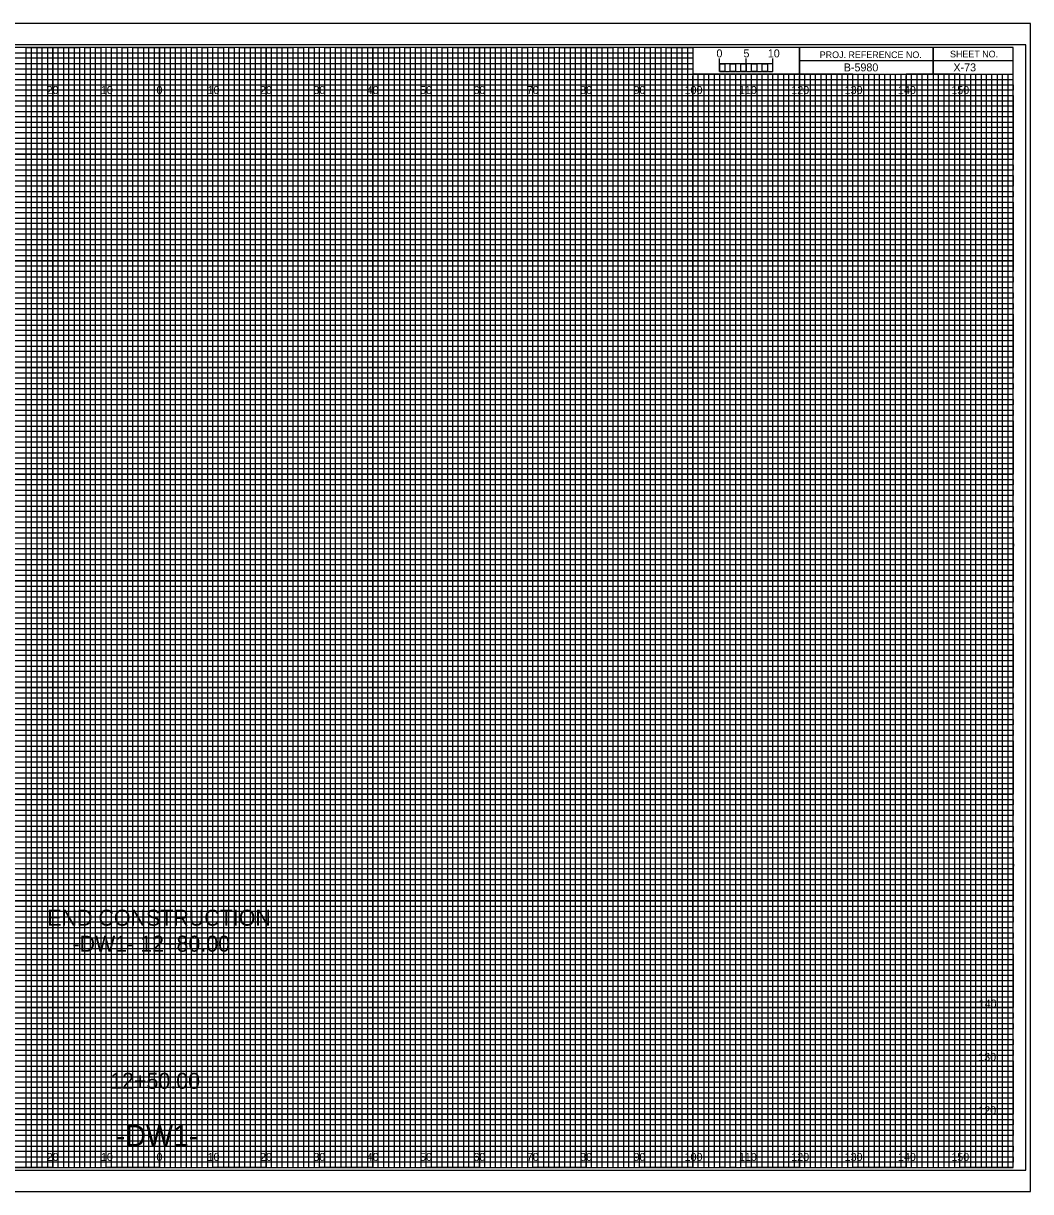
# Model space of a CAD drawing. Extents: x -13 to 323, y -5 to 434.
# Drawn here: x 134.5 to 323.3, y 215.5 to 434.5 of the extents above; entities that cross this region are included whole.
import ezdxf

# ---------------------------------------------------------------- set-up
doc = ezdxf.new("R2010")
doc.units = 0
for name, color, linetype in [('Exist Cross Section Cell', 7, 'Continuous'), ('Exist XS Center Line Elevation Label', 7, 'Continuous'), ('Exist XS Ground Line', 7, 'Continuous'), ('Prop CMT Pvmt Course 1', 7, 'Continuous'), ('Prop CMT Pvmt Course 1 Wedge', 7, 'Continuous'), ('Prop CMT Pvmt Course 2', 7, 'Continuous'), ('Prop CMT Pvmt Course 3', 7, 'Continuous'), ('Prop CMT Pvmt Surface', 7, 'Continuous'), ('Prop CMT Pvmt Surface Shoulder', 7, 'Continuous'), ('Prop CMT Shld Paved Course 1', 7, 'Continuous'), ('Prop CMT Shld Paved Course 2', 7, 'Continuous'), ('Prop CMT Shld Paved Course 3', 7, 'Continuous'), ('Prop CMT Slope Grass', 7, 'Continuous'), ('Prop CMT Subgrade Earthwork', 7, 'Continuous'), ('Prop XS Ditch Standard Text', 7, 'Continuous'), ('Prop XS SE Text', 7, 'Continuous'), ('Prop XS Side Slope Text', 7, 'Continuous')]:
    doc.layers.add(name, color=color, linetype=linetype)

msp = doc.modelspace()

# ---------------------------------------------------------------- linework, layer by layer
at = {"layer": 'Exist XS Center Line Elevation Label'}
for points in [[(125, 220), (135, 220), (135, 430), (145, 430), (145, 220), (155, 220), (155, 430), (165, 430), (165, 220), (175, 220), (175, 430), (185, 430), (185, 220), (195, 220), (195, 430), (205, 430), (205, 220), (215, 220), (215, 430), (225, 430), (225, 220), (235, 220), (235, 430), (245, 430), (245, 220), (255, 220), (255, 430), (259.93, 430), (260, 430), (260, 425), (264.99, 425), (264.99, 220), (275, 220), (275, 425), (285, 425), (285, 220), (295, 220), (295, 425), (305, 425), (305, 220), (315, 220), (315, 425)], [(0, 425), (275, 425)], [(0, 405), (320, 405), (320, 415), (0, 415)], [(0, 385), (320, 385), (320, 395), (0, 395)], [(0, 365), (320, 365), (320, 375), (0, 375)], [(0, 345), (320, 345), (320, 355), (0, 355)], [(0, 325), (320, 325), (320, 335), (0, 335)], [(0, 305), (320, 305), (320, 315), (0, 315)], [(0, 285), (320, 285), (320, 295), (0, 295)], [(0, 265), (320, 265), (320, 275), (0, 275)], [(0, 245), (320, 245), (320, 255), (0, 255)], [(0, 225), (320, 225), (320, 235), (0, 235)]]:
    msp.add_lwpolyline(points, dxfattribs=at)
at = {"layer": 'Exist XS Ground Line'}
for p, q in [((150, 430), (140, 430)), ((140, 430), (140, 220)), ((150, 220), (150, 430)), ((170, 430), (160, 430)), ((160, 430), (160, 220)), ((170, 220), (170, 430)), ((190, 430), (180, 430)), ((180, 430), (180, 220)), ((190, 220), (190, 430)), ((210, 430), (200, 430)), ((200, 430), (200, 220)), ((210, 220), (210, 430)), ((230, 430), (220, 430)), ((220, 430), (220, 220)), ((230, 220), (230, 430)), ((250, 430), (240, 430)), ((240, 430), (240, 220)), ((250, 220), (250, 430)), ((260, 430), (260, 220)), ((270, 220), (270, 425)), ((290, 425), (280, 425)), ((280, 425), (280, 220)), ((290, 220), (290, 425)), ((310, 425), (300, 425)), ((300, 425), (300, 220)), ((310, 220), (310, 425)), ((140, 220), (130, 220)), ((160, 220), (150, 220)), ((180, 220), (170, 220)), ((200, 220), (190, 220)), ((220, 220), (210, 220)), ((240, 220), (230, 220)), ((260, 220), (250, 220)), ((280, 220), (270, 220)), ((300, 220), (290, 220)), ((320, 220), (310, 220)), ((320, 220), (320, 220))]:
    msp.add_line(p, q, dxfattribs=at)
for points in [[(0, 420), (320, 420), (320, 410), (0, 410)], [(0, 400), (320, 400), (320, 390), (0, 390)], [(0, 380), (320, 380), (320, 370), (0, 370)], [(0, 360), (320, 360), (320, 350), (0, 350)], [(0, 340), (320, 340), (320, 330), (0, 330)], [(0, 320), (320, 320), (320, 310), (0, 310)], [(0, 300), (320, 300), (320, 290), (0, 290)], [(0, 280), (320, 280), (320, 270), (0, 270)], [(0, 260), (320, 260), (320, 250), (0, 250)], [(0, 240), (320, 240), (320, 230), (0, 230)]]:
    msp.add_lwpolyline(points, dxfattribs=at)
at = {"layer": 'Prop CMT Pvmt Course 2'}
for p, q in [((265, 425.49), (265, 427.9)), ((265, 426.9), (265, 427.9)), ((270, 425.49), (270, 427.9)), ((275, 425.49), (275, 427.9)), ((275, 426.9), (275, 427.9))]:
    msp.add_line(p, q, dxfattribs=at)
for points in [[(275, 426.9), (265, 426.9), (265, 425.49), (275, 425.49)], [(265, 426.9), (266, 426.9), (266, 425.49), (265, 425.49)], [(267, 426.9), (268, 426.9), (268, 425.49), (267, 425.49)], [(269, 426.9), (270, 426.9), (270, 425.49), (269, 425.49)], [(271, 426.9), (272, 426.9), (272, 425.49), (271, 425.49)], [(273, 426.9), (274, 426.9), (274, 425.49), (273, 425.49)]]:
    msp.add_lwpolyline(points, close=True, dxfattribs=at)
at = {"layer": 'Prop CMT Pvmt Course 3'}
msp.add_lwpolyline([(-13.4, 215.5), (323.3, 215.5), (323.3, 434.5), (-13.4, 434.5)], close=True, dxfattribs=at)
at = {"layer": 'Prop CMT Pvmt Surface'}
for p, q in [((140, 220), (140, 430)), ((150, 220), (150, 430)), ((160, 220), (160, 430)), ((170, 220), (170, 430)), ((180, 220), (180, 430)), ((190, 220), (190, 430)), ((200, 220), (200, 430)), ((210, 220), (210, 430)), ((220, 220), (220, 430)), ((230, 220), (230, 430)), ((240, 220), (240, 430)), ((250, 220), (250, 430)), ((260, 220), (260, 424.69)), ((270, 220), (270, 424.69)), ((280, 220), (280, 424.69)), ((290, 220), (290, 424.69)), ((300, 220), (300, 424.69)), ((310, 220), (310, 424.69)), ((0, 420), (320, 420)), ((0, 410), (320, 410)), ((0, 400), (320, 400)), ((0, 390), (320, 390)), ((0, 380), (320, 380)), ((0, 370), (320, 370)), ((0, 360), (320, 360)), ((0, 350), (320, 350)), ((0, 340), (320, 340)), ((0, 330), (320, 330)), ((0, 320), (320, 320)), ((0, 310), (320, 310)), ((0, 300), (320, 300)), ((0, 290), (320, 290)), ((0, 280), (320, 280)), ((0, 270), (320, 270)), ((0, 260), (320, 260)), ((0, 250), (320, 250)), ((0, 240), (320, 240)), ((0, 230), (320, 230))]:
    msp.add_line(p, q, dxfattribs=at)
at = {"layer": 'Prop CMT Pvmt Surface Shoulder'}
for p, q in [((323.3, 434.5), (-13.4, 434.5)), ((-13.4, 215.5), (323.3, 215.5))]:
    msp.add_line(p, q, dxfattribs=at)
at = {"layer": 'Prop CMT Shld Paved Course 1'}
for p, q in [((0, 429), (260, 429)), ((260, 427.98), (0, 427.98)), ((260, 429), (260, 427.98)), ((0, 427), (260, 427)), ((260, 425.89), (0, 425.89)), ((260, 427), (260, 425.89)), ((0, 424), (320, 424))]:
    msp.add_line(p, q, dxfattribs=at)
for points in [[(0, 423), (270, 423), (320, 423), (320, 422), (0, 422)], [(0, 421), (320, 421), (320, 419), (0, 419)], [(0, 418), (320, 418), (320, 417), (0, 416.98)], [(0, 416), (320, 416), (320, 414), (0, 414)], [(0, 413), (320, 413), (320, 412), (0, 412)], [(0, 411), (320, 411), (320, 409), (0, 409)], [(0, 408), (320, 408), (320, 407), (0, 407)], [(0, 406), (320, 406), (320, 404), (0, 404)], [(0, 403), (320, 403), (320, 402), (0, 402)], [(0, 401), (320, 401), (320, 399), (0, 399)], [(0, 398), (320, 398), (320, 397), (0, 397)], [(0, 396), (320, 396), (320, 393.95), (320, 393), (320, 392), (0, 392)], [(0, 394), (320, 394), (320, 393), (0, 393)], [(0, 391), (320, 391), (320, 389), (0, 389.03)], [(0, 389.03), (320, 389), (320, 388), (0, 388)], [(0, 387), (320, 387), (320, 386), (0, 386)], [(0, 384), (320, 384), (320, 383), (0, 383)], [(0, 382), (320, 382), (320, 381), (0, 381)], [(-0.07, 378.89), (320, 378.89), (320, 377.88), (-0.07, 377.88)], [(0, 377), (320, 377), (320, 376), (0, 376)], [(0, 374), (320, 374), (320, 373), (0, 373)], [(0, 372), (320, 372), (320, 371), (0, 371)], [(0, 369), (320, 369), (320, 368), (0, 368)], [(0, 367), (320, 367), (320, 366), (0, 366)], [(0, 364), (320, 364), (320, 363), (0, 363)], [(0, 362), (320, 362), (320, 361), (0, 361)], [(0, 359), (320, 359), (319.99, 357.98), (0, 358)], [(0, 357), (320, 357), (320, 356), (0, 356)], [(0, 354), (320, 354), (320, 353), (0, 353)], [(0, 352), (320, 352), (320, 351), (0, 351)], [(0, 349), (320, 349), (320, 348), (0, 348)], [(0, 347), (320, 347), (320, 346), (0, 346)], [(0, 344), (320, 344), (320, 343), (0, 343)], [(0, 342), (320, 342), (320, 341), (0, 341)], [(0, 339), (320, 339), (320, 338), (0, 338)], [(0, 336.99), (320.07, 336.91), (320, 336), (0, 336)], [(0, 334), (320, 334), (320, 333), (0, 333)], [(0, 332), (320, 332), (320, 331), (0, 331)], [(0, 329), (320, 329), (320, 328), (0, 328)], [(0, 327), (320, 327), (320, 326), (0, 326)], [(0, 324), (320, 324), (320, 323), (0, 323)], [(0, 322), (320, 322), (320, 321), (0, 321)], [(0, 319), (320, 319), (320, 318), (0, 318)], [(0, 317), (320, 317), (320, 316), (0, 316)], [(0, 314), (320, 314), (320, 313), (0, 313)], [(0, 312), (320, 312), (320, 311), (0, 311)], [(0, 309), (320, 309), (320, 308), (0, 308)], [(0, 307), (320, 307), (320, 306), (0, 306)], [(0, 304), (320, 304), (320, 303), (0, 303)], [(0, 302), (320, 302), (320, 301), (0, 301)], [(0, 299), (320, 299), (319.99, 297.98), (0, 298)], [(0, 297), (320, 297), (320, 296), (0, 296)], [(0, 294), (320, 294), (320, 293), (0, 293)], [(0, 292), (320, 292), (320, 291), (0, 291)], [(0, 289), (320, 289), (320, 288), (0, 288)], [(0, 287), (320, 287), (320, 286), (0, 286)], [(0, 284), (320, 284), (320, 283), (0, 283)], [(0, 282), (320, 282), (320, 281), (0, 281)], [(0, 279), (320, 279), (320, 278), (0, 278)], [(0, 276.99), (320.07, 276.91), (320, 276), (0, 276)], [(0, 274), (320, 274), (320, 273), (0, 273)], [(0, 272), (320, 272), (320, 271), (0, 271)], [(0, 269), (320, 269), (320, 268), (0, 268)], [(0, 267), (320, 267), (320, 266), (0, 266)], [(0, 264), (320, 264), (320, 263), (0, 263)], [(0, 262), (320, 262), (320, 261), (0, 261)], [(0, 259), (320, 259), (320, 258), (0, 258)], [(0, 257), (320, 257), (320, 256), (0, 256)], [(0, 254), (320, 254), (320, 253), (0, 253)], [(0, 252), (320, 252), (320, 251), (0, 251)], [(0, 249), (320, 249), (320, 248), (0, 248)], [(0, 247), (320, 247), (320, 246), (0, 246)], [(0, 244), (320, 244), (320, 243), (0, 243)], [(0, 242), (320, 242), (320, 241), (0, 241)], [(0, 239), (320, 239), (320, 238), (0, 238)], [(0, 237), (320, 237), (320, 236), (0, 236)], [(0, 234), (320, 234), (320, 233), (0, 233)], [(0, 232), (320, 232), (320, 231), (0, 231)], [(0, 229), (320, 229), (320, 228), (0, 228)], [(0, 227), (320, 227), (320, 226), (0, 226)], [(0, 224), (320, 224), (320, 223), (0, 223)], [(0, 222), (320, 222), (320, 221), (0, 221)]]:
    msp.add_lwpolyline(points, dxfattribs=at)
at = {"layer": 'Prop CMT Shld Paved Course 2'}
for p, q in [((305, 430), (305, 425)), ((305, 425), (305, 430)), ((280, 427.5), (280, 425)), ((320, 427.49), (280, 427.49)), ((280, 425), (320, 425))]:
    msp.add_line(p, q, dxfattribs=at)
for points in [[(320, 430), (0, 430), (0, 220), (320, 220)], [(280, 430), (260, 430), (260, 425.03), (280, 425.03)], [(320, 430), (280, 430), (280, 425), (320, 425)]]:
    msp.add_lwpolyline(points, close=True, dxfattribs=at)
at = {"layer": 'Prop CMT Shld Paved Course 3'}
for p, q in [((267, 425), (266.01, 425)), ((266.01, 425), (266.01, 220)), ((267, 220), (267, 425)), ((269, 425), (268, 425)), ((268, 425), (268, 220)), ((269, 220), (269, 425)), ((266.01, 220), (265, 220)), ((268, 220), (267, 220))]:
    msp.add_line(p, q, dxfattribs=at)
for points in [[(135, 220), (136, 220), (136, 430), (137, 430), (137, 220)], [(137, 220), (138, 220), (138, 430), (139, 430), (139, 220)], [(140, 220), (141, 220), (141, 430), (142, 430), (142, 220)], [(142, 220), (143, 220), (143, 430), (144, 430), (144, 220)], [(145, 220), (146, 220), (146, 430), (147, 430), (147, 220)], [(147, 220), (148, 220), (148, 430), (149, 430), (149, 220)], [(150, 220), (151, 220), (151, 430), (152, 430), (152, 220)], [(152, 220), (153, 220), (153, 430), (154, 430), (154, 220)], [(155, 220), (156, 220), (156, 430), (157, 430), (157, 220)], [(157, 220), (158, 220), (158, 430), (159, 430), (159, 220)], [(160, 220), (161, 220), (161, 430), (162, 430), (162, 220)], [(162, 220), (163, 220), (163, 430), (164, 430), (164, 220)], [(165, 220), (166, 220), (166, 430), (167, 430), (167, 220)], [(167, 220), (168, 220), (168, 430), (169, 430), (169, 220)], [(170, 220), (171, 220), (171, 430), (172, 430), (172, 220)], [(172, 220), (173, 220), (173, 430), (174, 430), (174, 220)], [(175, 220), (176, 220), (176, 430), (177, 430), (177, 220)], [(177, 220), (178, 220), (178, 430), (179, 430), (179, 220)], [(180, 220), (181, 220), (181, 430), (182, 430), (182, 220)], [(182, 220), (183, 220), (183, 430), (184, 430), (184, 220)], [(185, 220), (186, 220), (186, 430), (187, 430), (187, 220)], [(187, 220), (188, 220), (188, 430), (189, 430), (189, 220)], [(190, 220), (191, 220), (191, 430), (192, 430), (192, 220)], [(192, 220), (193, 220), (193, 430), (194, 430), (194, 220)], [(195, 220), (196, 220), (196, 430), (197, 430), (197, 220)], [(197, 220), (198, 220), (198, 430), (199, 430), (199, 220)], [(200, 220), (201, 220), (201, 430), (202, 430), (202, 220)], [(202, 220), (203, 220), (203, 430), (204, 430), (204, 220)], [(205, 220), (206, 220), (206, 430), (207, 430), (207, 220)], [(207, 220), (208, 220), (208, 430), (209, 430), (209, 220)], [(210, 220), (211, 220), (211, 430), (212, 430), (212, 220)], [(212, 220), (213, 220), (213, 430), (214, 430), (214, 220)], [(215, 220), (216, 220), (216, 430), (217, 430), (217, 220)], [(217, 220), (218, 220), (218, 430), (219, 430), (219, 220)], [(220, 220), (221, 220), (221, 430), (222, 430), (222, 220)], [(222, 220), (223, 220), (223, 430), (224, 430), (224, 220)], [(225, 220), (226, 220), (226, 430), (227, 430), (227, 220)], [(227, 220), (228, 220), (228, 430), (229, 430), (229, 220)], [(230, 220), (231, 220), (231, 430), (232, 430), (232, 220)], [(232, 220), (233, 220), (233, 430), (234, 430), (234, 220)], [(235, 220), (236, 220), (236, 430), (237, 430), (237, 220)], [(237, 220), (238, 220), (238, 430), (239, 430), (239, 220)], [(240, 220), (241, 220), (241, 430), (242, 430), (242, 220)], [(242, 220), (243, 220), (243, 430), (244, 430), (244, 220)], [(245, 220), (246, 220), (246, 430), (247, 430), (247, 220)], [(247, 220), (248, 220), (248, 430), (249, 430), (249, 220)], [(250, 220), (251, 220), (251, 430), (252, 430), (252, 220)], [(252, 220), (253, 220), (253, 430), (254, 430), (254, 220)], [(255, 220), (256, 220), (256, 430), (257, 430), (257, 220)], [(257, 220), (258, 220), (258, 430), (259, 430), (259, 220)], [(260, 220), (261, 220), (261, 425), (262.02, 425), (262.02, 220)], [(262, 220), (263, 220), (263, 425), (263.99, 425), (263.99, 220)], [(270, 220), (270.98, 220), (270.98, 425), (272, 425), (272, 220)], [(272, 220), (273, 220), (273, 425), (274.05, 425), (274.05, 220)], [(275, 220), (276, 220), (276, 425), (277, 425), (277, 220)], [(277, 220), (278, 220), (278, 425), (279, 425), (279, 220)], [(280, 220), (281, 220), (281, 425), (282, 425), (282, 220)], [(282, 220), (283, 220), (283, 425), (284, 425), (284, 220)], [(285, 220), (286, 220), (286, 425), (287, 425), (287, 220)], [(287, 220), (288, 220), (288, 425), (289, 425), (289, 220)], [(290, 220), (291, 220), (291, 425), (292, 425), (292, 220)], [(292, 220), (293, 220), (293, 425), (294, 425), (294, 220)], [(295, 220), (296, 220), (296, 425), (297, 425), (297, 220)], [(297, 220), (298, 220), (298, 425), (299, 425), (299, 220)], [(300, 220), (301, 220), (301, 425), (302, 425), (302, 220)], [(302, 220), (303, 220), (303, 425), (304, 425), (304, 220)], [(305, 220), (306, 220), (306, 425), (307, 425), (307, 220)], [(307, 220), (308, 220), (308, 425), (309, 425), (309, 220)], [(310, 220), (311, 220), (311, 425), (312, 425), (312, 220)], [(312, 220), (313, 220), (313, 425), (314, 425), (314, 220)], [(315, 220), (316, 220), (316, 425), (317, 425), (317, 220)], [(317, 220), (318, 220), (318, 425), (319, 425), (319, 220)]]:
    msp.add_lwpolyline(points, dxfattribs=at)
at = {"layer": 'Prop CMT Subgrade Earthwork'}
msp.add_lwpolyline([(-10.8, 219.5), (322.4, 219.5), (322.4, 430.5), (-10.8, 430.5)], close=True, dxfattribs=at)

# ---------------------------------------------------------------- texts
at = {"layer": 'Exist Cross Section Cell'}
for s, p in [('20', (138.86, 421.25)), ('10', (149.04, 421.25)), ('0', (159.45, 421.25)), ('0', (159.45, 421.25)), ('10', (169.04, 421.25)), ('20', (178.86, 421.25)), ('30', (188.86, 421.25)), ('40', (198.86, 421.25)), ('50', (208.86, 421.25)), ('60', (218.86, 421.25)), ('70', (228.86, 421.25)), ('80', (238.86, 421.25)), ('90', (248.86, 421.25)), ('100', (258.44, 421.25)), ('110', (268.62, 421.25)), ('120', (278.44, 421.25)), ('130', (288.44, 421.25)), ('140', (298.44, 421.25)), ('150', (308.44, 421.25)), ('20', (138.86, 221.25)), ('10', (149.04, 221.25)), ('0', (159.45, 221.25)), ('0', (159.45, 221.25)), ('10', (169.04, 221.25)), ('20', (178.86, 221.25)), ('30', (188.86, 221.25)), ('40', (198.86, 221.25)), ('50', (208.86, 221.25)), ('60', (218.86, 221.25)), ('70', (228.86, 221.25)), ('80', (238.86, 221.25)), ('90', (248.86, 221.25)), ('100', (258.44, 221.25)), ('110', (268.62, 221.25)), ('120', (278.44, 221.25)), ('130', (288.44, 221.25)), ('140', (298.44, 221.25)), ('150', (308.44, 221.25))]:
    msp.add_text(s, height=1.5, dxfattribs=at).set_placement(p)
at = {"layer": 'Prop CMT Pvmt Course 1'}
for s, p in [('140', (313.57, 250)), ('130', (313.49, 240)), ('120', (313.5, 230))]:
    msp.add_text(s, height=1.5, dxfattribs=at).set_placement(p)
at = {"layer": 'Prop CMT Pvmt Course 1 Wedge'}
for s, p in [('5', (269.47, 428.12)), ('10', (274.04, 428.12))]:
    msp.add_text(s, height=1.5, dxfattribs=at).set_placement(p)
at = {"layer": 'Prop CMT Pvmt Course 2'}
msp.add_text('0', height=1.5, dxfattribs=at).set_placement((264.41, 428.12))
at = {"layer": 'Prop CMT Shld Paved Course 2'}
for s, p in [('PROJ. REFERENCE NO.', (283.77, 427.99)), ('SHEET NO.', (308.19, 428.12))]:
    msp.add_text(s, height=1.25, dxfattribs=at).set_placement(p)
at = {"layer": 'Prop CMT Slope Grass'}
for s, p in [('END CONSTRUCTION', (138.99, 265.35)), ('-DW1- 12+80.00', (143.7, 260.48)), ('12+50.00', (150.77, 234.78))]:
    msp.add_text(s, height=3, dxfattribs=at).set_placement(p)
at = {"layer": 'Prop XS Ditch Standard Text'}
msp.add_text('-DW1-', height=4, dxfattribs=at).set_placement((151.85, 224))
at = {"layer": 'Prop XS SE Text'}
msp.add_text('X-73', height=1.5, dxfattribs=at).set_placement((308.83, 425.5))
at = {"layer": 'Prop XS Side Slope Text'}
msp.add_text('B-5980', height=1.5, dxfattribs=at).set_placement((288.28, 425.5))

doc.saveas('drawing.dxf')
